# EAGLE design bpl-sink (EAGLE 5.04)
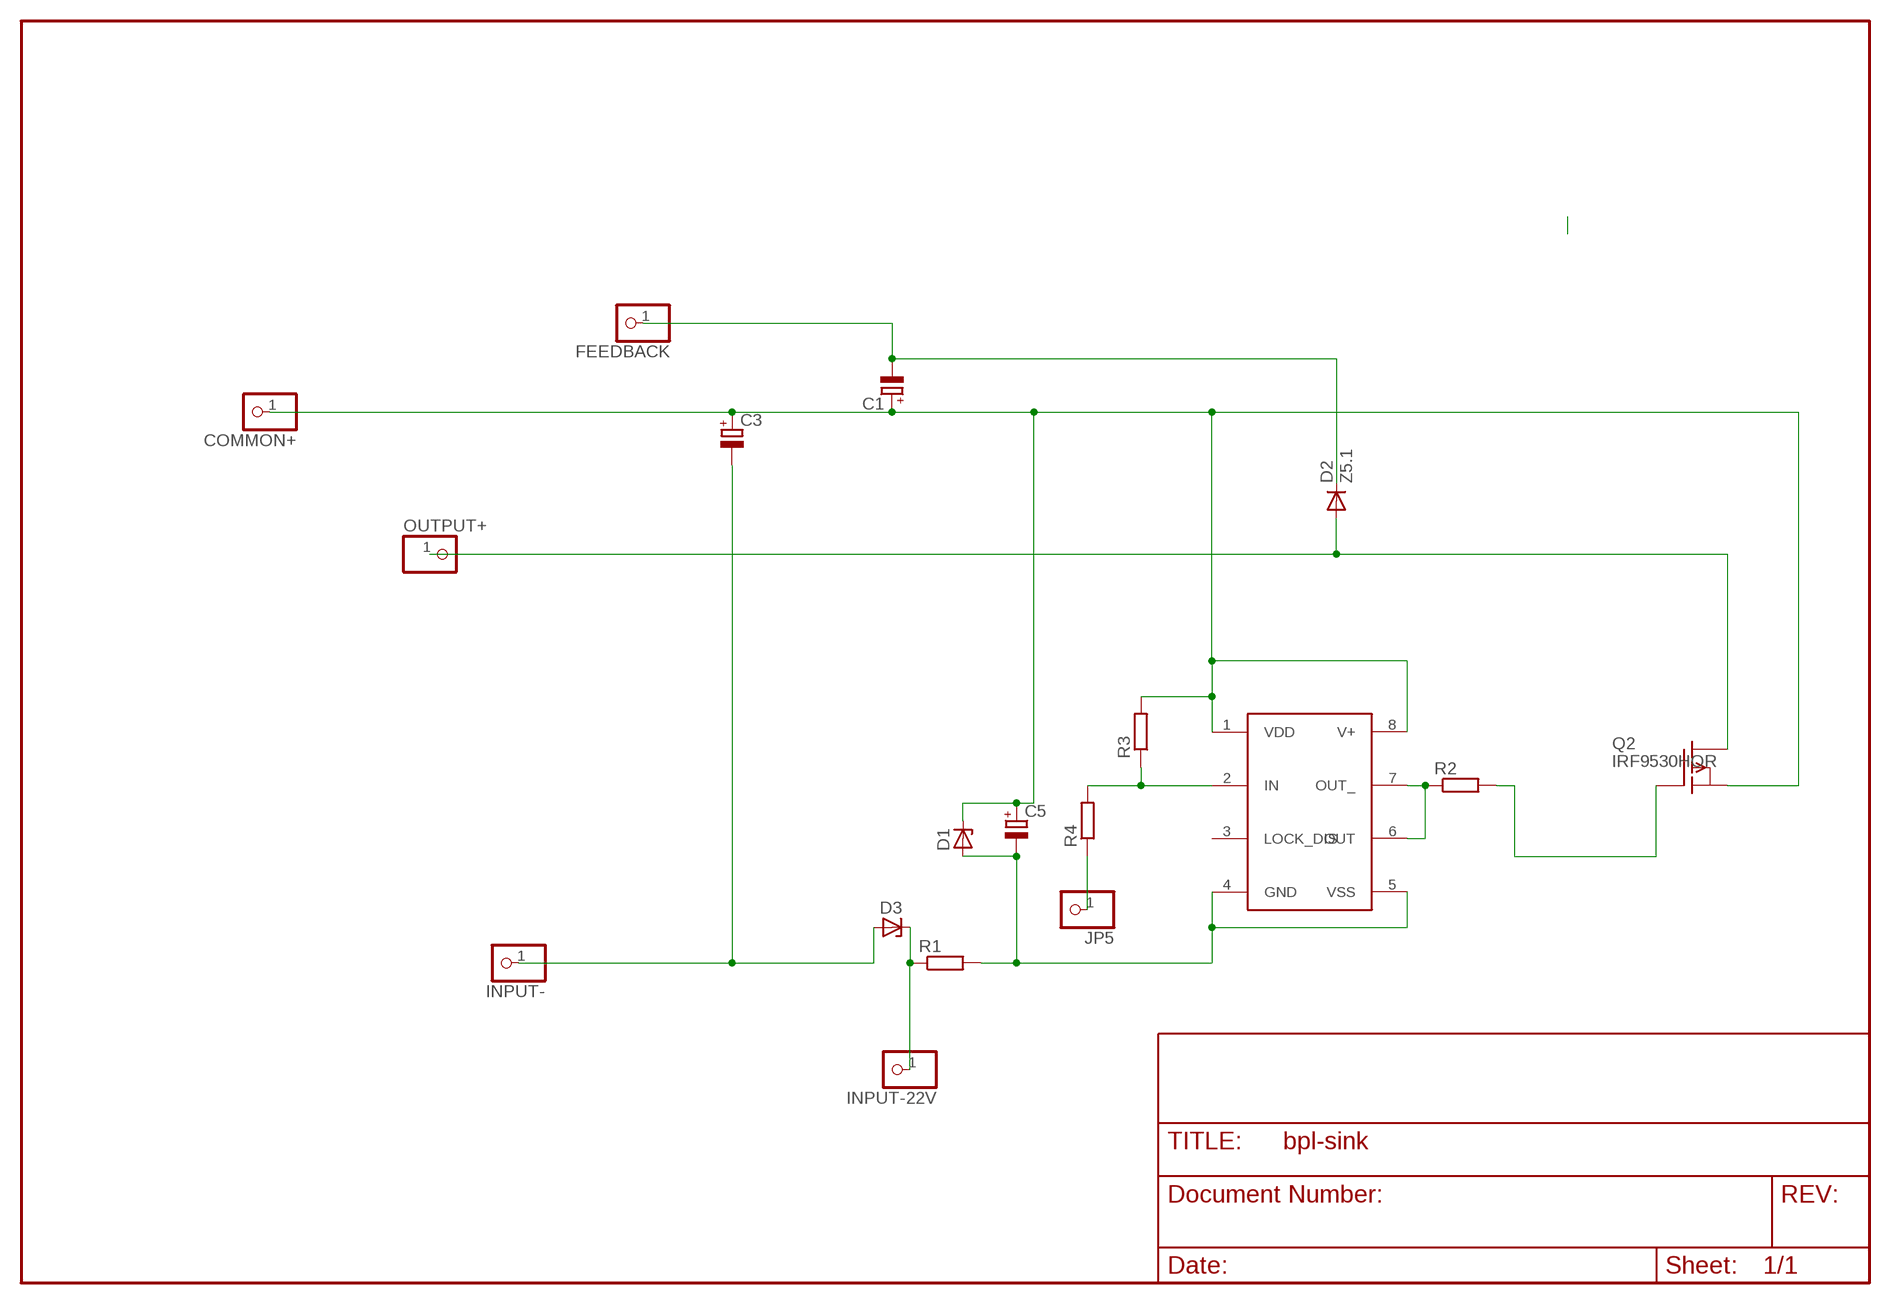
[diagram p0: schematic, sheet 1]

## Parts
C1  CPOL-EUE2.5-7  [E2,5-7]
C3  CPOL-EUE2-4  [E2-4]
C5  CPOL-EUE2-4  [E2-4]
COMMON+  PINHD-1X1  [1X01]
D1  ZENER-DIODEZD-2.5  [ZDIO-2.5]
D2  Z5.1  DIODE-D-2.5  [D-2.5]
D3  ZENER-DIODEZD-2.5  [ZDIO-2.5]
FEEDBACK  PINHD-1X1  [1X01]
IC1  TC4432X  [SO-08]
INPUT-  PINHD-1X1  [1X01]
INPUT-22V  PINHD-1X1  [1X01]
JP5  PINHD-1X1  [1X01]
OUTPUT+  PINHD-1X1  [1X01]
Q2  IRF9530HOR  [TO220]
R1  R-EU_0207/10  [0207/10]
R2  R-EU_R1206  [R1206]
R3  R-EU_R1206  [R1206]
R4  R-EU_R1206  [R1206]

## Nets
GND: C5.- D1.A IC1.4(GND) IC1.5(VSS) R1.2
N$1: IC1.2(IN) R3.1 R4.2
N$2: C1.- D2.C FEEDBACK.1
N$3: IC1.6(OUT) IC1.7(OUT_) R2.1
N$5: D3.C INPUT-22V.1 R1.1
N$6: Q2.1(G) R2.2
N$9: C3.- D3.A INPUT-.1
N$10: D2.A OUTPUT+.1 Q2.2(D)
N$11: JP5.1 R4.1
VDD: C1.+ C3.+ C5.+ COMMON+.1 D1.C IC1.1(VDD) IC1.8(V+) Q2.3(S) R3.2
Unconnected: IC1.3(LOCK_DIS)

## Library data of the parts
C1 C3 C5 = rcl(2):CPOL-EU: POLARIZED CAPACITOR, European symbol
COMMON+ FEEDBACK INPUT- INPUT-22V JP5 OUTPUT+ = pinhead:PINHD-1X1: PIN HEADER
D1 D3 = diode-1:ZENER-DIODE: Z-Diode
D2 = diode:DIODE-: DIODE
IC1 = microchip:TC4432
Q2 = transistor-fet:IRF9530: P-Channel Enhancement MOSFET (HEXFET); -100V; -12A; 0,3Ohm
R1-R4 = rcl-2:R-EU_: RESISTOR, European symbol

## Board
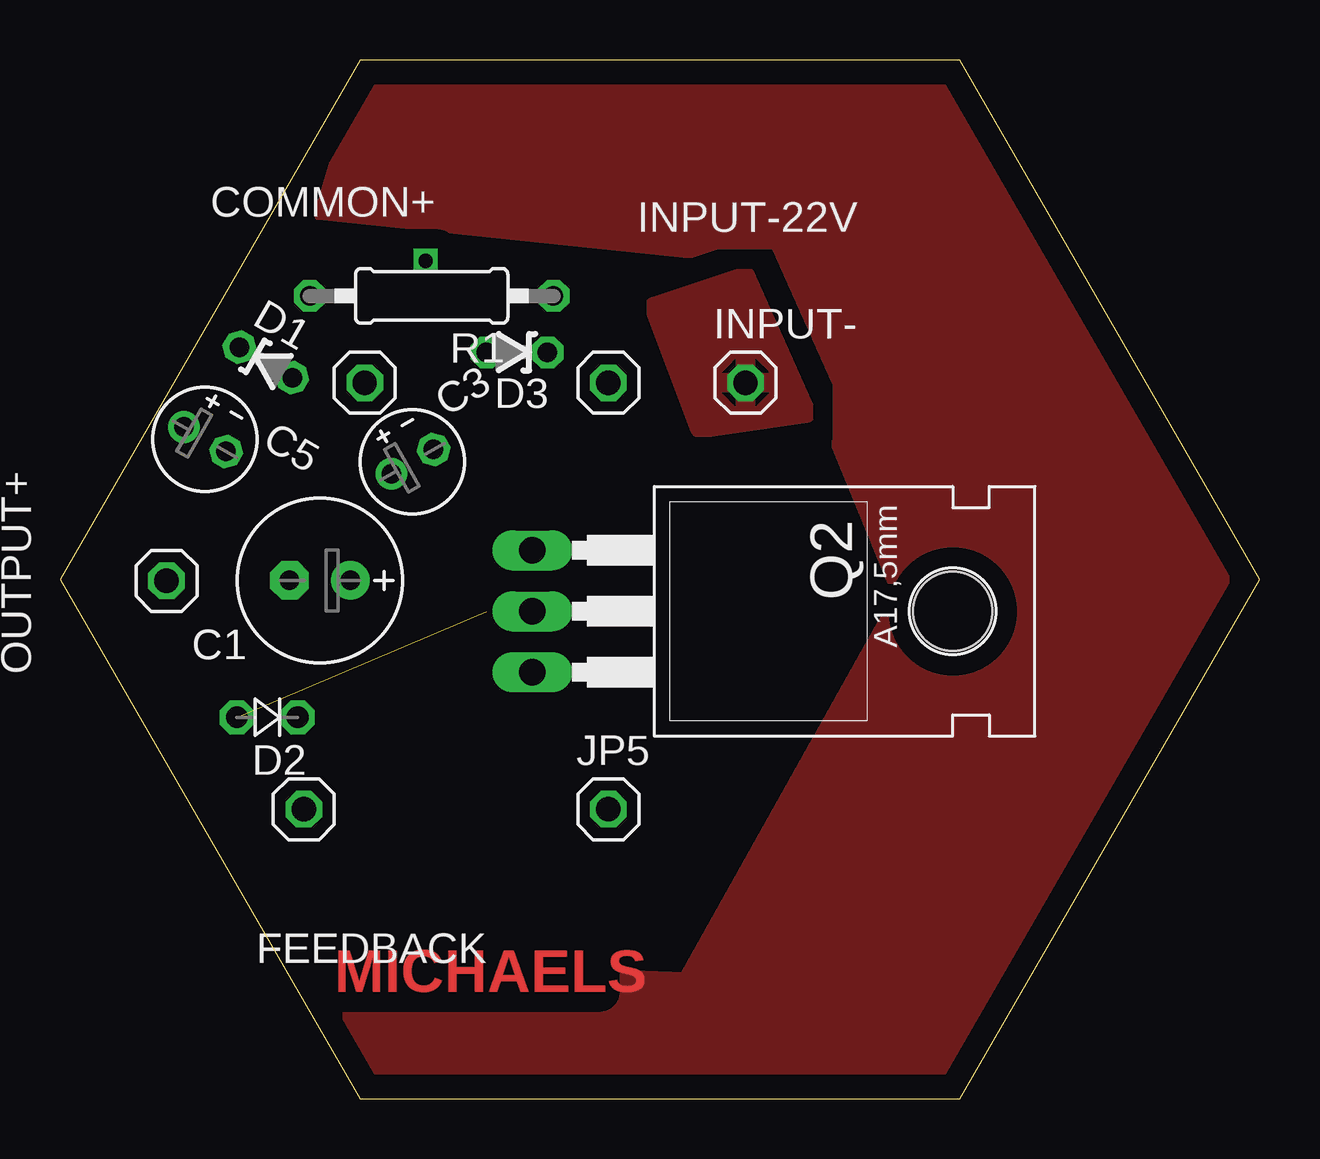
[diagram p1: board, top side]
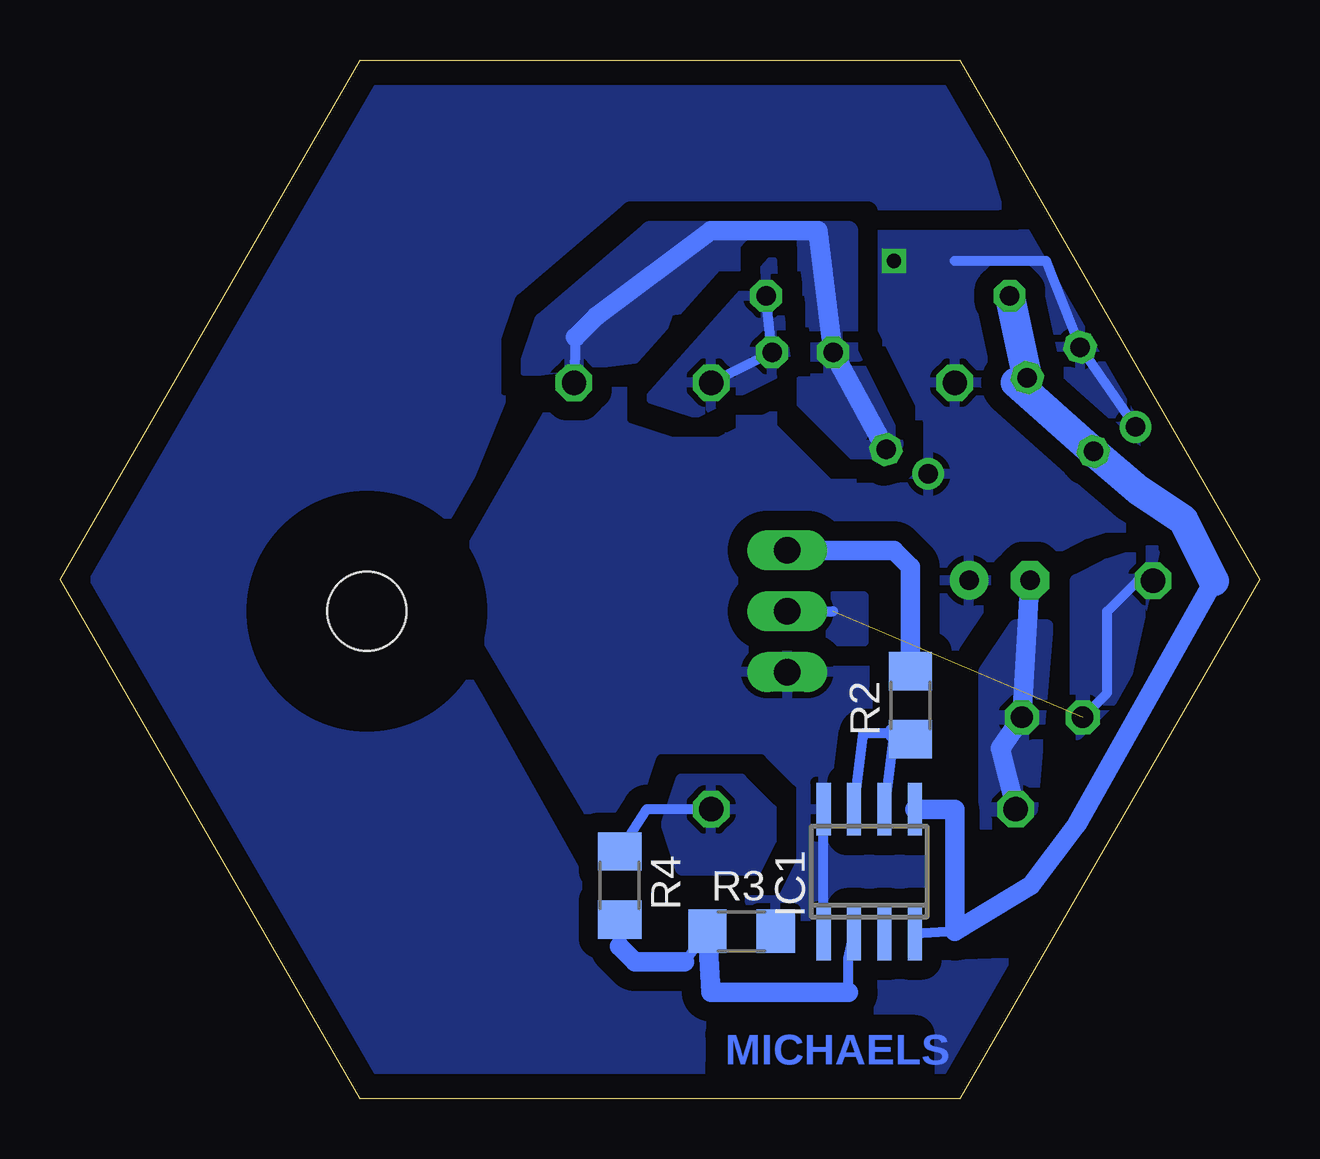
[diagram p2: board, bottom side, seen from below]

Size 50 x 43.3 mm. Coordinates in mm from the lower left corner, seen from the top.
Outline: 12.5,0 37.5,0 50,21.65 37.5,43.3 12.5,43.3 0,21.65 12.5,0
Copper layers (1*16): Top 0.035mm / dielectric 1.5mm / Bottom 0.035mm
Design rules "default": minimum track width 10mil, minimum drill 24mil, track to track 8mil, track to pad 8mil, pad to pad 8mil, via to via 8mil, smd to smd 8mil, copper to edge 40mil, drill to drill 8mil, minimum pad ring 10mil, minimum via ring 8mil, stop-mask expansion 4mil, vias tented up to drill 0mil, thermal gap 10mil

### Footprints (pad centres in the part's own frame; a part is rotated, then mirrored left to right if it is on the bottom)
E2,5-7 = drill 0.813 pad 1.6 round: + -1.27,0 | drill 0.813 pad 1.6 octagon: - 1.27,0
E2-4 = drill 0.813 pad 1.27 round: + -1.016,0 | drill 0.813 pad 1.27 octagon: - 1.016,0
1X01 = drill 1.016 octagon: 1 0,0
ZDIO-2.5 = drill 0.813 octagon: A 1.27,0; C -1.27,0
D-2.5 = drill 0.9 octagon: A 1.27,0; C -1.27,0
SO-08 = smd 0.6 x 2.2: 1 -1.905,-2.6; 2 -0.635,-2.6; 3 0.635,-2.6; 4 1.905,-2.6; 5 1.905,2.6; 6 0.635,2.6; 7 -0.635,2.6; 8 -1.905,2.6
TO220 = drill 1.118 long: 1 -2.54,-6.35; 2 0,-6.35; 3 2.54,-6.35 | hole 3.302: 0,11.176
0207/10 = drill 0.813 octagon: 1 -5.08,0; 2 5.08,0
R1206 = smd 1.6 x 1.803: 1 -1.422,0; 2 1.422,0

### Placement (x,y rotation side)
C1  10.84,21.6 180 top
C3  14.69,26.55 30 top
C5  6.04,27.49 330 top
COMMON+  12.7,29.84 0 top
D1  8.58,30.69 330 top
D2  8.64,15.9 180 top
D3  19.05,31.11 180 top
FEEDBACK  10.16,12.06 0 top
IC1  16.27,9.47 0 bottom
INPUT-  28.57,29.84 0 top
INPUT-22V  22.86,29.84 0 top
JP5  22.86,12.06 0 top
OUTPUT+  4.45,21.59 0 top
Q2  26.04,20.32 270 top
R1  15.49,33.47 180 top
R2  14.55,16.4 90 bottom
R3  21.59,6.99 0 bottom
R4  26.67,8.89 270 bottom

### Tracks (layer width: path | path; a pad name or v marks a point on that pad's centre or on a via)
GND
  Bottom 0.406: 12.7,6.99 IC1.4 | 10.16,29.84 D1.A
  Bottom 0.813: IC1.5 12.7,12.06 12.7,6.99 9.53,8.89 7.62,11.43 1.91,21.59
  Bottom 1.27: 10.16,29.84 C5.- 5.08,25.4 3.17,24.13 1.91,21.59 | D1.A R1.2
N$1
  Bottom 0.406: 26.67,6.35 R4.2 | R3.1 23.98,5.71 | 17.14,4.45 17.14,5.84 IC1.2
  Bottom 0.813: 26.67,6.35 26.04,5.71 23.98,5.71 | R3.1 22.86,4.45 17.14,4.45
N$2
  Bottom 0.813: FEEDBACK.1 10.79,14.61 D2.C C1.-
  pour Bottom (isolate 0.61, rank 2): 10.16,19.68 11.43,17.78 11.43,11.43 9.53,12.06 8.89,19.68
N$3
  Bottom 0.406: IC1.6 15.24,15.24 16.51,15.24 IC1.7
  Bottom 0.813: 15.24,15.24 R2.1
N$4
  pour Bottom (isolate 0.813, rank 6): 12.7,43.18 38.1,43.18 43.81,31.11 49.53,21.59 37.47,0 13.34,0 9.53,5.71 26.04,5.08 34.92,20.95 29.21,34.92 10.79,36.83
  pour Top (isolate 0.813, rank 6): 12.7,43.18 38.1,43.18 43.81,31.11 49.53,21.59 37.47,0 13.34,0 9.53,5.71 26.04,5.08 34.92,20.95 29.21,34.92 10.79,36.83
N$5
  Bottom 0.406: R1.1 D3.C INPUT-22V.1
  pour Bottom (isolate 0.406): 20.32,34.92 25.4,29.21 23.5,28.57 19.68,30.48
N$6
  Bottom 0.813: R2.2 14.55,22.18 15.24,22.86 Q2.1
N$9
  Bottom 0.406: D3.A 17.86,31.75 | 27.63,32.63 27.94,32.38 | 28.51,31.75 INPUT-.1
  Bottom 0.813: C3.- D3.A 18.41,36.2 22.86,36.2 27.63,32.63 28.51,31.75
  pour Bottom (isolate 0.813, rank 2): 30.48,30.48 29.84,32.38 25.4,36.2 17.14,36.2 17.14,31.11 15.24,27.3 16.51,26.67 19.05,29.21 19.68,33.66 24.77,33.02 25.4,31.11
  pour Top (isolate 0.813, rank 2): 31.11,28.57 28.57,34.29 24.77,33.02 26.67,27.94
N$10  (1 unrouted)
  Bottom 0.406: OUTPUT+.1 5.08,21.59 6.35,20.32 6.35,16.92 D2.A | Q2.2 17.78,20.32
  pour Bottom (isolate 0.61): 4.45,22.86 6.35,22.23 7.62,21.59 7.62,15.24 5.71,17.14
  pour Bottom (isolate 0.813): 20.32,20.32 17.78,20.95 16.51,20.95 16.51,19.68 16.51,19.05 17.78,19.05 19.68,20.32
N$11
  Bottom 0.406: JP5.1 25.55,12.06 R4.1
  pour Bottom (isolate 0.406): 20.32,12.06 21.59,13.34 24.13,13.34 24.77,11.43 24.13,9.53 20.95,9.53 20.32,10.79
VDD  (via drill 0.6)
  Bottom 0.406: 12.7,34.92 8.89,34.92 D1.C C5.+ | IC1.1 IC1.8
  other vias: 15.24,34.92
  pour Bottom (isolate 0.813, rank 3): 10.16,36 25.4,36 33.66,21.59 25.4,7.62 8.89,7.62 0.64,21.59 8.89,36.2

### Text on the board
Top: MICHAELS
Bottom: MICHAELS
